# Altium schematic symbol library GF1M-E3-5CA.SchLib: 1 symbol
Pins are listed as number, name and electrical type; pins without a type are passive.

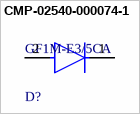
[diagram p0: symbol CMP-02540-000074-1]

## CMP-02540-000074-1
designator D?, comment GF1M-E3/5CA
DIODE GEN PURP 1KV 1A DO214BA; Forward Voltage: 1.2V; Reverse Recovery Time-Max: 2s; Recovery Time: 3000ns; Peak Non-Repetitive Surge Current: 30A; Max Reverse Current: 5uA; Reverse Recovery Time: 2us; Element Configuration: Single
footprint FP-GF1M-E3-5CA-MFG
pins: 1 C, 2 A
